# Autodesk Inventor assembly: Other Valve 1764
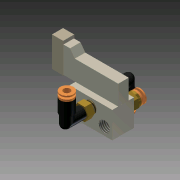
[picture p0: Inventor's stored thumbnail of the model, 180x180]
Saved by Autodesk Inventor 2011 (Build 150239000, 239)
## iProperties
Created: 2010-02
Part Number: Other Valve 1764
Document SubType Name: Assembly
Designer: jgehrig
Author: jgehrig
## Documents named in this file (5)
- R:\CAD Archives\Pnewmatics\Valve\Other Valve 1764.iam
- R:\CAD Archives\Pnewmatics\Valve\Valve Base 1764.ipt
- R:\CAD Archives\Pnewmatics\Valve\Valve Part 1764.ipt
- R:\CAD Archives\Pnewmatics\Pnematics Bend Piece\Bend Piece 1764.iam
- R:\CAD Archives\Pnewmatics\pnewmatic screw\Pnematic Screw 1764.iam
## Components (5 placed, 4 different names)
1. Valve Base 1764:1 — Flush:1, Mate:1, Flush:2, Insert:1, Insert:2, Angle:2, Insert:3
2. Valve Part 1764:1 — Flush:1, Mate:1, Flush:2, Angle:1
3. Bend Piece 1764:1 [sub-assembly] — Insert:1, Angle:1
4. Bend Piece 1764:2 [sub-assembly] — Insert:2, Angle:2
5. Pnematic Screw 1764:1 [sub-assembly] — Insert:3
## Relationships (8: Insert 3, Flush 2, Angle 2, Mate 1)
- Flush:1: Valve Base 1764:1 ↔ Valve Part 1764:1
- Mate:1: Valve Base 1764:1 ↔ Valve Part 1764:1
- Flush:2: Valve Base 1764:1 ↔ Valve Part 1764:1
- Insert:1: Valve Base 1764:1 ↔ Bend Piece 1764:1
- Angle:1: Valve Part 1764:1 ↔ Bend Piece 1764:1
- Insert:2: Valve Base 1764:1 ↔ Bend Piece 1764:2
- Angle:2: Valve Base 1764:1 ↔ Bend Piece 1764:2
- Insert:3: Valve Base 1764:1 ↔ Pnematic Screw 1764:1
